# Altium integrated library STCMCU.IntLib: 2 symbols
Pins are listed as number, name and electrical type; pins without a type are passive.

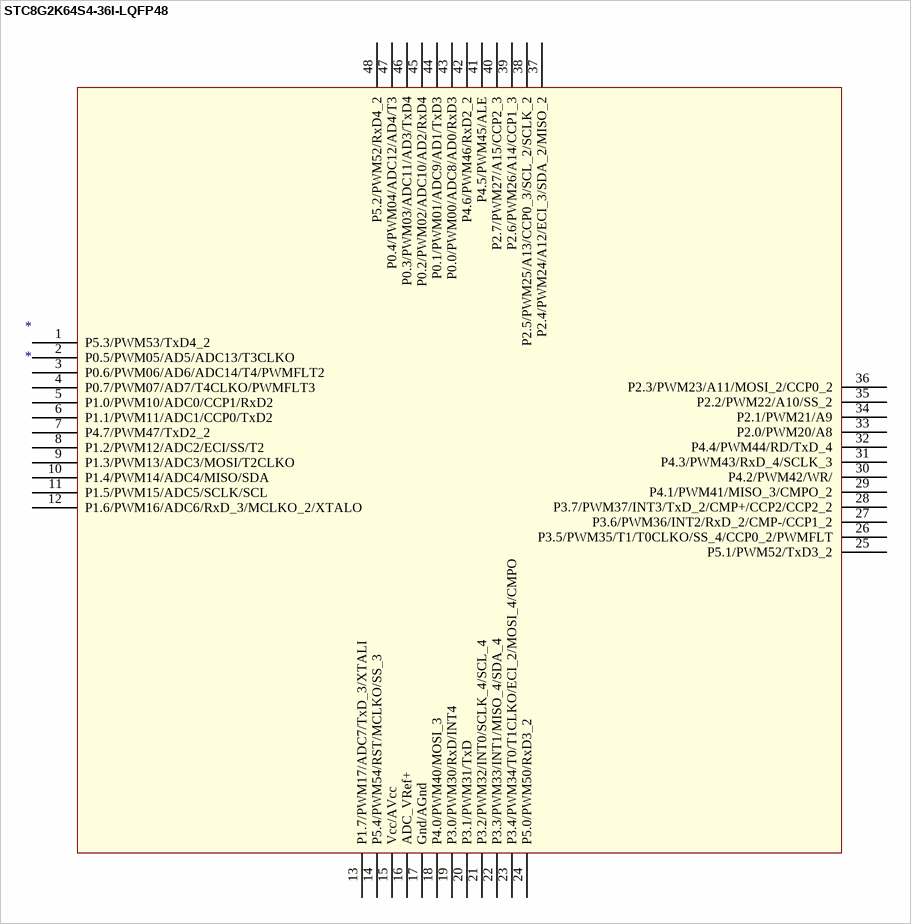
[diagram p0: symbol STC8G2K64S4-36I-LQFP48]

## STC8G2K64S4-36I-LQFP48
designator *
footprint LQFP900X900X160-48N (TSQFP, 48-Leads, Body 7.00x7.00mm, Pitch 0.50mm, IPC Medium Density)
pins: 1 P5.3/PWM53/TxD4_2, 2 P0.5/PWM05/AD5/ADC13/T3CLKO, 3 P0.6/PWM06/AD6/ADC14/T4/PWMFLT2, 4 P0.7/PWM07/AD7/T4CLKO/PWMFLT3, 5 P1.0/PWM10/ADC0/CCP1/RxD2, 6 P1.1/PWM11/ADC1/CCP0/TxD2, 7 P4.7/PWM47/TxD2_2, 8 P1.2/PWM12/ADC2/ECI/SS/T2, 9 P1.3/PWM13/ADC3/MOSI/T2CLKO, 10 P1.4/PWM14/ADC4/MISO/SDA, 11 P1.5/PWM15/ADC5/SCLK/SCL, 12 P1.6/PWM16/ADC6/RxD_3/MCLKO_2/XTALO, 13 P1.7/PWM17/ADC7/TxD_3/XTALI, 14 P5.4/PWM54/RST/MCLKO/SS_3, 15 Vcc/AVcc (power), 16 ADC_VRef+ (power), 17 Gnd/AGnd (power), 18 P4.0/PWM40/MOSI_3, 19 P3.0/PWM30/RxD/INT4, 20 P3.1/PWM31/TxD, 21 P3.2/PWM32/INT0/SCLK_4/SCL_4, 22 P3.3/PWM33/INT1/MISO_4/SDA_4, 23 P3.4/PWM34/T0/T1CLKO/ECI_2/MOSI_4/CMPO, 24 P5.0/PWM50/RxD3_2, 25 P5.1/PWM52/TxD3_2, 26 P3.5/PWM35/T1/T0CLKO/SS_4/CCP0_2/PWMFLT, 27 P3.6/PWM36/INT2/RxD_2/CMP-/CCP1_2, 28 P3.7/PWM37/INT3/TxD_2/CMP+/CCP2/CCP2_2, 29 P4.1/PWM41/MISO_3/CMPO_2, 30 P4.2/PWM42/WR/, 31 P4.3/PWM43/RxD_4/SCLK_3, 32 P4.4/PWM44/RD/TxD_4, 33 P2.0/PWM20/A8, 34 P2.1/PWM21/A9, 35 P2.2/PWM22/A10/SS_2, 36 P2.3/PWM23/A11/MOSI_2/CCP0_2, 37 P2.4/PWM24/A12/ECI_3/SDA_2/MISO_2, 38 P2.5/PWM25/A13/CCP0_3/SCL_2/SCLK_2, 39 P2.6/PWM26/A14/CCP1_3, 40 P2.7/PWM27/A15/CCP2_3, 41 P4.5/PWM45/ALE, 42 P4.6/PWM46/RxD2_2, 43 P0.0/PWM00/ADC8/AD0/RxD3, 44 P0.1/PWM01/ADC9/AD1/TxD3, 45 P0.2/PWM02/ADC10/AD2/RxD4, 46 P0.3/PWM03/ADC11/AD3/TxD4, 47 P0.4/PWM04/ADC12/AD4/T3, 48 P5.2/PWM52/RxD4_2

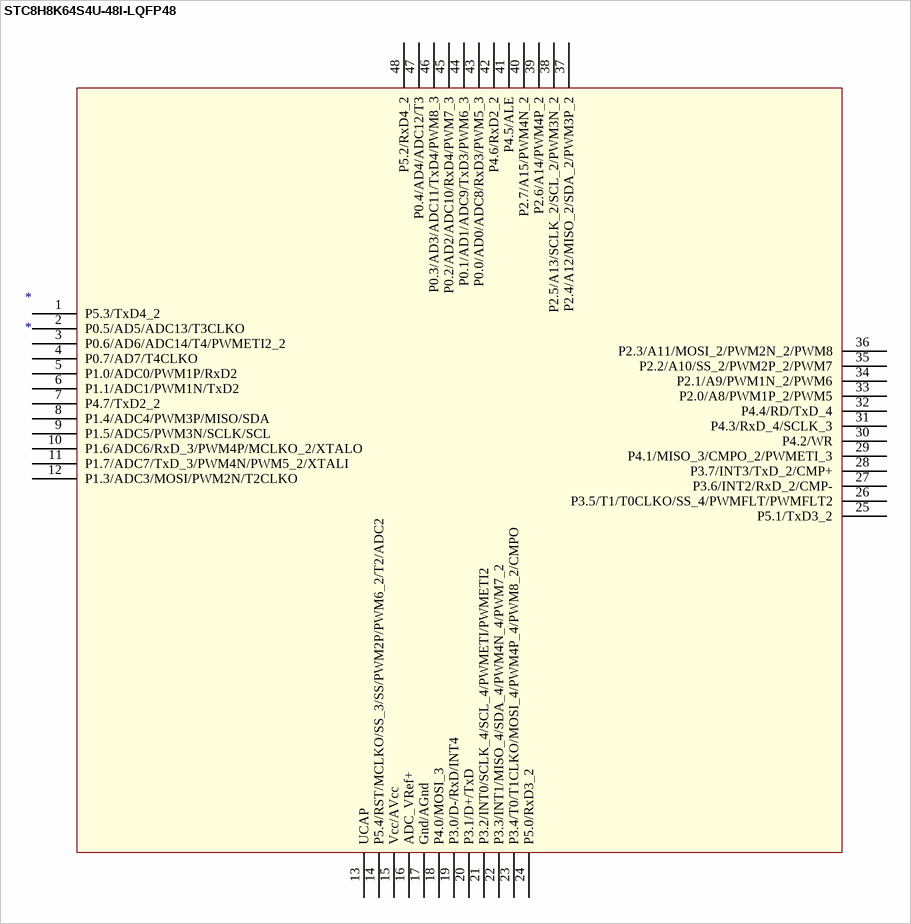
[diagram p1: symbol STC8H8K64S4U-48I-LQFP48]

## STC8H8K64S4U-48I-LQFP48
designator *
footprint LQFP900X900X160-48N (TSQFP, 48-Leads, Body 7.00x7.00mm, Pitch 0.50mm, IPC Medium Density)
pins: 1 P5.3/TxD4_2, 2 P0.5/AD5/ADC13/T3CLKO, 3 P0.6/AD6/ADC14/T4/PWMETI2_2, 4 P0.7/AD7/T4CLKO, 5 P1.0/ADC0/PWM1P/RxD2, 6 P1.1/ADC1/PWM1N/TxD2, 7 P4.7/TxD2_2, 8 P1.4/ADC4/PWM3P/MISO/SDA, 9 P1.5/ADC5/PWM3N/SCLK/SCL, 10 P1.6/ADC6/RxD_3/PWM4P/MCLKO_2/XTALO, 11 P1.7/ADC7/TxD_3/PWM4N/PWM5_2/XTALI, 12 P1.3/ADC3/MOSI/PWM2N/T2CLKO, 13 UCAP, 14 P5.4/RST/MCLKO/SS_3/SS/PWM2P/PWM6_2/T2/ADC2, 15 Vcc/AVcc (power), 16 ADC_VRef+ (power), 17 Gnd/AGnd (power), 18 P4.0/MOSI_3, 19 P3.0/D-/RxD/INT4, 20 P3.1/D+/TxD, 21 P3.2/INT0/SCLK_4/SCL_4/PWMETI/PWMETI2, 22 P3.3/INT1/MISO_4/SDA_4/PWM4N_4/PWM7_2, 23 P3.4/T0/T1CLKO/MOSI_4/PWM4P_4/PWM8_2/CMPO, 24 P5.0/RxD3_2, 25 P5.1/TxD3_2, 26 P3.5/T1/T0CLKO/SS_4/PWMFLT/PWMFLT2, 27 P3.6/INT2/RxD_2/CMP-, 28 P3.7/INT3/TxD_2/CMP+, 29 P4.1/MISO_3/CMPO_2/PWMETI_3, 30 P4.2/WR, 31 P4.3/RxD_4/SCLK_3, 32 P4.4/RD/TxD_4, 33 P2.0/A8/PWM1P_2/PWM5, 34 P2.1/A9/PWM1N_2/PWM6, 35 P2.2/A10/SS_2/PWM2P_2/PWM7, 36 P2.3/A11/MOSI_2/PWM2N_2/PWM8, 37 P2.4/A12/MISO_2/SDA_2/PWM3P_2, 38 P2.5/A13/SCLK_2/SCL_2/PWM3N_2, 39 P2.6/A14/PWM4P_2, 40 P2.7/A15/PWM4N_2, 41 P4.5/ALE, 42 P4.6/RxD2_2, 43 P0.0/AD0/ADC8/RxD3/PWM5_3, 44 P0.1/AD1/ADC9/TxD3/PWM6_3, 45 P0.2/AD2/ADC10/RxD4/PWM7_3, 46 P0.3/AD3/ADC11/TxD4/PWM8_3, 47 P0.4/AD4/ADC12/T3, 48 P5.2/RxD4_2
